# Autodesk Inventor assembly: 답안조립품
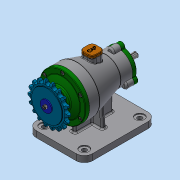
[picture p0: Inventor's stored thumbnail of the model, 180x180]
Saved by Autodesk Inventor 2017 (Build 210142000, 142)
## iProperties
Part Number: 답안조립품
Material: 일반
Document SubType Name: Assembly
Designer: user
Author: user
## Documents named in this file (16)
- C:\Users\user\Desktop\711006V1002\답안조립품.iam
- C:\Users\user\Desktop\711006V1002\1.본체.ipt
- C:\Users\user\Desktop\711006V1002\앞커버.ipt
- C:\Users\user\Desktop\711006V1002\뒤커버.ipt
- C:\Users\user\Desktop\711006V1002\베어링 6200.ipt
- C:\Users\user\Desktop\711006V1002\베어링 6203.ipt
- C:\Users\user\Desktop\711006V1002\축.ipt
- C:\Users\user\Desktop\711006V1002\키 5x5.ipt
- 키 5 x 5.ipt
- C:\Users\user\Desktop\711006V1002\오일 실 17x30x8.ipt
- C:\Users\user\Desktop\711006V1002\오일 실 10x20x7.ipt
- C:\Users\user\Desktop\711006V1002\볼트 M4.ipt
- 볼트 M4 x 12.ipt
- C:\Users\user\Desktop\711006V1002\마개.ipt
- C:\Users\user\Desktop\711006V1002\스프로킷.ipt
- C:\Users\user\Desktop\711006V1002\와셔.ipt
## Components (1 placed, 1 different names)
1. 1.본체:1 — 각도:3
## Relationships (1: Angle 1)
- 각도:3 [Angle]: 1.본체:1
